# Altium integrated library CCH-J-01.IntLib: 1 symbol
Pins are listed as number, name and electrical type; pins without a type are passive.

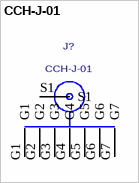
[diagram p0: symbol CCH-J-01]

## CCH-J-01
designator J?
SINGLE COMPLIANT COAX ASSEMBLY.; MANUFACTURER: SAMTEC
footprint CCH-J-01
pins: G1, G2, G3, G4, G5, G6, G7, S1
